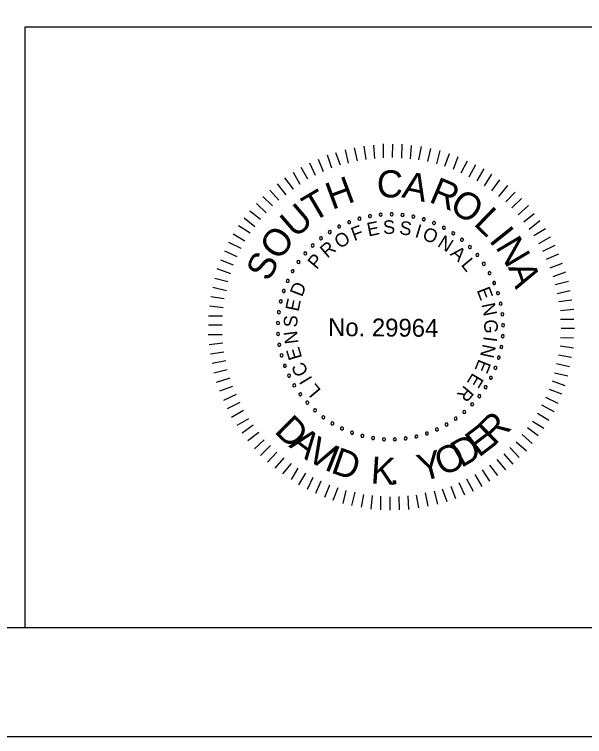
# Model space of a CAD drawing. Extents: x -133.1 to -97, y -110.1 to -88.1.
# Drawn here: x -110.556 to -107.945, y -110.103 to -106.796 of the extents above; entities that cross this region are included whole.
import ezdxf

# ---------------------------------------------------------------- set-up
doc = ezdxf.new("R2010")
doc.units = 0
for name, color, linetype in [('BR_BORDER LINES', 7, 'Continuous'), ('BR_TEXT', 7, 'Continuous'), ('Level 31', 7, 'Continuous')]:
    doc.layers.add(name, color=color, linetype=linetype)

msp = doc.modelspace()

# ---------------------------------------------------------------- linework, layer by layer
at = {"layer": 'BR_BORDER LINES'}
for p, q in [((-110.5071, -106.8526), (-105.1419, -106.8526)), ((-110.5071, -109.6027), (-110.5071, -106.8526)), ((-131.3076, -109.6027), (-97.6416, -109.6027))]:
    msp.add_line(p, q, dxfattribs=at)
at = {"layer": 'BR_TEXT'}
for p, q in [((-108.9059, -107.4556), (-108.9097, -107.3946)), ((-108.8664, -107.4533), (-108.8658, -107.389)), ((-108.8243, -107.4511), (-108.8238, -107.3893)), ((-108.7823, -107.454), (-108.78, -107.3897)), ((-108.742, -107.4569), (-108.7372, -107.396)), ((-109.0623, -107.4869), (-109.0842, -107.4292)), ((-109.0262, -107.4769), (-109.0394, -107.4159)), ((-108.9849, -107.467), (-108.999, -107.4076)), ((-108.9454, -107.4595), (-108.9543, -107.3986)), ((-108.7034, -107.4615), (-108.6926, -107.4007)), ((-108.6631, -107.4696), (-108.6489, -107.4105)), ((-108.622, -107.4802), (-108.606, -107.4195)), ((-109.1406, -107.5163), (-109.1642, -107.4603)), ((-109.1019, -107.4995), (-109.1229, -107.4409)), ((-108.5852, -107.4908), (-108.5633, -107.4335)), ((-108.5458, -107.504), (-108.5239, -107.4459)), ((-109.2122, -107.5509), (-109.2426, -107.4966)), ((-109.1777, -107.5332), (-109.2039, -107.4771)), ((-108.5099, -107.5215), (-108.482, -107.4659)), ((-108.474, -107.539), (-108.4427, -107.4834)), ((-109.2475, -107.5746), (-109.278, -107.5203)), ((-108.4364, -107.5573), (-108.4042, -107.5035)), ((-108.4031, -107.5816), (-108.3692, -107.5278)), ((-109.2786, -107.5958), (-109.3177, -107.5449)), ((-108.3699, -107.6033), (-108.3334, -107.553)), ((-109.3123, -107.6213), (-109.3522, -107.5712)), ((-108.3375, -107.6293), (-108.2968, -107.5799)), ((-109.3745, -107.6731), (-109.4188, -107.629)), ((-109.3451, -107.6459), (-109.3868, -107.6009)), ((-108.3059, -107.6545), (-108.2627, -107.6102)), ((-109.4039, -107.7038), (-109.4474, -107.6614)), ((-108.2779, -107.6822), (-108.2346, -107.6388)), ((-108.2498, -107.7133), (-108.2022, -107.6716)), ((-109.4551, -107.7686), (-109.5046, -107.7287)), ((-109.4291, -107.7353), (-109.4786, -107.6963)), ((-108.2226, -107.7453), (-108.1759, -107.707)), ((-108.1988, -107.779), (-108.1496, -107.7399)), ((-109.4768, -107.7976), (-109.5306, -107.7645)), ((-108.1768, -107.8083), (-108.1242, -107.7761)), ((-109.5012, -107.8343), (-109.5549, -107.8021)), ((-108.1548, -107.8454), (-108.1013, -107.8141)), ((-109.5186, -107.8685), (-109.575, -107.8405)), ((-108.137, -107.8799), (-108.0793, -107.8529)), ((-109.5361, -107.9052), (-109.5933, -107.8798)), ((-108.1193, -107.9169), (-108.0624, -107.8925)), ((-109.5536, -107.9437), (-109.6117, -107.9218)), ((-108.1025, -107.9557), (-108.0456, -107.9347)), ((-109.5659, -107.9839), (-109.6275, -107.9611)), ((-108.0891, -107.9961), (-108.0314, -107.9743)), ((-109.5782, -108.0199), (-109.639, -108.0048)), ((-108.079, -108.0322), (-108.0189, -108.0181)), ((-109.5854, -108.0619), (-109.6479, -108.0459)), ((-108.0708, -108.0744), (-108.0106, -108.0594)), ((-109.596, -108.0978), (-109.6569, -108.0896)), ((-108.0625, -108.1105), (-108.0033, -108.1032)), ((-109.6006, -108.139), (-109.6624, -108.1316)), ((-108.056, -108.1517), (-107.995, -108.1454)), ((-109.6035, -108.1784), (-109.6679, -108.1779)), ((-108.0546, -108.1912), (-107.9945, -108.1917)), ((-109.6056, -108.2196), (-109.6682, -108.219)), ((-108.0524, -108.2324), (-107.9915, -108.2329)), ((-109.6042, -108.2625), (-109.6686, -108.2637)), ((-108.0553, -108.2753), (-107.9952, -108.2775)), ((-109.602, -108.3012), (-109.6638, -108.3083)), ((-108.0574, -108.3139), (-107.9965, -108.3221)), ((-109.598, -108.3424), (-109.659, -108.3513)), ((-108.0645, -108.355), (-108.0054, -108.365)), ((-109.5881, -108.3819), (-109.6508, -108.3951)), ((-108.0735, -108.3944), (-108.0135, -108.4087)), ((-109.5815, -108.4241), (-109.6426, -108.4381)), ((-108.0824, -108.4364), (-108.0224, -108.4515)), ((-109.5698, -108.461), (-109.6318, -108.482)), ((-108.093, -108.4732), (-108.0357, -108.4951)), ((-109.5582, -108.4997), (-109.6167, -108.5207)), ((-108.107, -108.5117), (-108.0506, -108.5337)), ((-109.5413, -108.5368), (-109.599, -108.5638)), ((-108.1245, -108.5485), (-108.0681, -108.5764)), ((-109.5244, -108.573), (-109.5813, -108.6025)), ((-108.1428, -108.5844), (-108.0856, -108.6149)), ((-109.5076, -108.61), (-109.5619, -108.6413)), ((-108.1612, -108.6211), (-108.1082, -108.6533)), ((-109.4838, -108.6471), (-109.5382, -108.6784)), ((-109.4626, -108.6765), (-109.5127, -108.713)), ((-108.2063, -108.6868), (-108.1577, -108.7242)), ((-108.1838, -108.6579), (-108.1317, -108.69)), ((-109.4372, -108.7101), (-109.4873, -108.7492)), ((-108.2306, -108.7201), (-108.1846, -108.76)), ((-109.4125, -108.7438), (-109.4567, -108.7847)), ((-108.2583, -108.7533), (-108.2115, -108.7949)), ((-109.3836, -108.7698), (-109.4286, -108.8149)), ((-108.2869, -108.7789), (-108.2444, -108.8247)), ((-109.3547, -108.8001), (-109.3971, -108.8461)), ((-108.3155, -108.8087), (-108.273, -108.8553)), ((-109.3222, -108.8261), (-109.363, -108.873)), ((-109.289, -108.8521), (-109.3289, -108.8998)), ((-108.3474, -108.8341), (-108.3075, -108.8817)), ((-109.2583, -108.8738), (-109.2896, -108.9259)), ((-108.4139, -108.8808), (-108.3808, -108.9334)), ((-108.3802, -108.8596), (-108.3446, -108.908)), ((-109.2233, -108.8964), (-109.2546, -108.9502)), ((-109.1891, -108.9164), (-109.2162, -108.972)), ((-108.4475, -108.9028), (-108.4162, -108.9571)), ((-109.1523, -108.9339), (-109.1769, -108.9895)), ((-109.1139, -108.9514), (-109.1358, -109.0079)), ((-108.5216, -108.9391), (-108.4947, -108.9951)), ((-108.4855, -108.9222), (-108.455, -108.9783)), ((-109.0745, -108.9637), (-109.0973, -109.0219)), ((-109.0386, -108.9761), (-109.0528, -109.0351)), ((-108.9974, -108.9832), (-109.0126, -109.0449)), ((-108.6344, -108.9794), (-108.6194, -109.0387)), ((-108.5974, -108.9676), (-108.5764, -109.0262)), ((-108.5578, -108.956), (-108.5368, -109.0128)), ((-108.9581, -108.9947), (-108.968, -109.053)), ((-108.9186, -108.9993), (-108.9234, -109.0611)), ((-108.8792, -109.0022), (-108.8797, -109.064)), ((-108.8372, -109.0052), (-108.8377, -109.0661)), ((-108.7951, -109.0029), (-108.7939, -109.0648)), ((-108.7547, -109.0007), (-108.7509, -109.0625)), ((-108.7161, -108.9967), (-108.7062, -109.0552)), ((-108.6756, -108.9859), (-108.6624, -109.0478))]:
    msp.add_line(p, q, dxfattribs=at)
for centre, start, end in [((-108.9763, -107.7311), 16.1422, 196.1422), ((-108.9278, -107.7196), 10.6038, 190.6038), ((-108.9278, -107.7196), 190.6038, 10.6038), ((-108.8784, -107.7129), 5.0653, 185.0653), ((-108.8784, -107.7129), 185.0653, 5.0653), ((-108.8286, -107.711), 359.5268, 179.5268), ((-108.8286, -107.711), 179.5268, 359.5268), ((-108.7789, -107.714), 173.9884, 353.9884), ((-108.7789, -107.714), 353.9884, 173.9884), ((-108.7296, -107.7217), 168.4499, 348.4499), ((-108.7296, -107.7217), 348.4499, 168.4499), ((-108.6814, -107.7341), 342.9114, 162.9114), ((-109.0689, -107.7676), 27.2191, 207.2191), ((-109.0235, -107.7471), 21.6807, 201.6807), ((-109.0235, -107.7471), 201.6807, 21.6807), ((-108.9763, -107.7311), 196.1422, 16.1422), ((-108.6814, -107.7341), 162.9114, 342.9114), ((-108.6345, -107.7511), 157.373, 337.373), ((-108.6345, -107.7511), 337.373, 157.373), ((-109.1121, -107.7925), 32.7576, 212.7576), ((-109.1121, -107.7925), 212.7576, 32.7576), ((-109.0689, -107.7676), 207.2191, 27.2191), ((-108.5896, -107.7726), 151.8345, 331.8345), ((-108.5896, -107.7726), 331.8345, 151.8345), ((-108.5469, -107.7983), 146.2961, 326.2961), ((-108.5469, -107.7983), 326.2961, 146.2961), ((-109.1527, -107.8213), 38.2961, 218.2961), ((-109.1527, -107.8213), 218.2961, 38.2961), ((-108.5069, -107.828), 140.7576, 320.7576), ((-108.5069, -107.828), 320.7576, 140.7576), ((-109.1903, -107.854), 43.8345, 223.8345), ((-109.1903, -107.854), 223.8345, 43.8345), ((-108.4699, -107.8614), 135.2191, 315.2191), ((-108.4699, -107.8614), 315.2191, 135.2191), ((-109.2246, -107.8901), 49.373, 229.373), ((-109.2246, -107.8901), 229.373, 49.373), ((-108.4363, -107.8982), 129.6807, 309.6807), ((-108.4363, -107.8982), 309.6807, 129.6807), ((-109.2553, -107.9294), 54.9114, 234.9114), ((-109.2553, -107.9294), 234.9114, 54.9114), ((-108.4065, -107.9381), 124.1422, 304.1422), ((-108.4065, -107.9381), 304.1422, 124.1422), ((-109.282, -107.9715), 60.4499, 240.4499), ((-109.282, -107.9715), 240.4499, 60.4499), ((-108.3806, -107.9807), 118.6038, 298.6038), ((-108.3806, -107.9807), 298.6038, 118.6038), ((-109.3045, -108.0159), 65.9884, 245.9884), ((-109.3045, -108.0159), 245.9884, 65.9884), ((-108.359, -108.0256), 113.0653, 293.0653), ((-108.359, -108.0256), 293.0653, 113.0653), ((-109.3227, -108.0623), 71.5268, 251.5268), ((-109.3227, -108.0623), 251.5268, 71.5268), ((-108.3418, -108.0724), 107.5268, 287.5268), ((-108.3418, -108.0724), 287.5268, 107.5268), ((-109.3363, -108.1103), 77.0653, 257.0653), ((-109.3363, -108.1103), 257.0653, 77.0653), ((-108.3292, -108.1206), 101.9884, 281.9884), ((-108.3292, -108.1206), 281.9884, 101.9884), ((-109.3452, -108.1593), 82.6038, 262.6038), ((-109.3452, -108.1593), 262.6038, 82.6038), ((-108.3213, -108.1698), 96.4499, 276.4499), ((-108.3213, -108.1698), 276.4499, 96.4499), ((-109.3493, -108.209), 88.1422, 268.1422), ((-109.3493, -108.209), 268.1422, 88.1422), ((-108.3182, -108.2195), 90.9114, 270.9114), ((-108.3182, -108.2195), 270.9114, 90.9114), ((-109.3486, -108.2588), 93.6807, 273.6807), ((-109.3486, -108.2588), 273.6807, 93.6807), ((-108.3199, -108.2693), 85.373, 265.373), ((-108.3199, -108.2693), 265.373, 85.373), ((-109.3431, -108.3083), 99.2191, 279.2191), ((-109.3431, -108.3083), 279.2191, 99.2191), ((-108.3265, -108.3187), 79.8345, 259.8345), ((-108.3265, -108.3187), 259.8345, 79.8345), ((-109.3328, -108.3571), 104.7576, 284.7576), ((-109.3328, -108.3571), 284.7576, 104.7576), ((-108.3377, -108.3673), 74.2961, 254.2961), ((-108.3377, -108.3673), 254.2961, 74.2961), ((-109.3179, -108.4046), 110.2961, 290.2961), ((-109.3179, -108.4046), 290.2961, 110.2961), ((-108.3536, -108.4145), 68.7576, 248.7576), ((-108.3536, -108.4145), 248.7576, 68.7576), ((-109.2985, -108.4505), 115.8345, 295.8345), ((-109.2985, -108.4505), 295.8345, 115.8345), ((-108.374, -108.46), 63.2191, 243.2191), ((-108.374, -108.46), 243.2191, 63.2191), ((-109.2747, -108.4943), 121.373, 301.373), ((-109.2747, -108.4943), 301.373, 121.373), ((-108.3986, -108.5033), 57.6807, 237.6807), ((-108.3986, -108.5033), 237.6807, 57.6807), ((-109.2468, -108.5356), 126.9114, 306.9114), ((-109.2468, -108.5356), 306.9114, 126.9114), ((-108.4273, -108.544), 52.1422, 232.1422), ((-108.4273, -108.544), 232.1422, 52.1422), ((-109.2151, -108.574), 132.4499, 312.4499), ((-109.2151, -108.574), 312.4499, 132.4499), ((-108.4599, -108.5818), 46.6038, 226.6038), ((-108.4599, -108.5818), 226.6038, 46.6038), ((-109.1798, -108.6092), 137.9884, 317.9884), ((-109.1798, -108.6092), 317.9884, 137.9884), ((-108.4959, -108.6162), 41.0653, 221.0653), ((-108.4959, -108.6162), 221.0653, 41.0653), ((-109.1413, -108.6408), 143.5268, 323.5268), ((-109.1413, -108.6408), 323.5268, 143.5268), ((-108.5351, -108.647), 35.5268, 215.5268), ((-108.5351, -108.647), 215.5268, 35.5268), ((-109.0999, -108.6685), 149.0653, 329.0653), ((-109.0999, -108.6685), 329.0653, 149.0653), ((-109.056, -108.6921), 334.6038, 154.6038), ((-108.577, -108.6739), 29.9884, 209.9884), ((-108.577, -108.6739), 209.9884, 29.9884), ((-109.056, -108.6921), 154.6038, 334.6038), ((-109.01, -108.7114), 160.1422, 340.1422), ((-109.01, -108.7114), 340.1422, 160.1422), ((-108.9624, -108.7261), 345.6807, 165.6807), ((-108.6677, -108.7149), 18.9114, 198.9114), ((-108.6677, -108.7149), 198.9114, 18.9114), ((-108.6214, -108.6966), 24.4499, 204.4499), ((-108.6214, -108.6966), 204.4499, 24.4499), ((-108.9624, -108.7261), 165.6807, 345.6807), ((-108.9136, -108.7362), 171.2191, 351.2191), ((-108.9136, -108.7362), 351.2191, 171.2191), ((-108.8641, -108.7415), 356.7576, 176.7576), ((-108.8641, -108.7415), 176.7576, 356.7576), ((-108.8142, -108.742), 2.2961, 182.2961), ((-108.8142, -108.742), 182.2961, 2.2961), ((-108.7646, -108.7377), 7.8345, 187.8345), ((-108.7646, -108.7377), 187.8345, 7.8345), ((-108.7156, -108.7287), 13.373, 193.373), ((-108.7156, -108.7287), 193.373, 13.373)]:
    msp.add_arc(centre, 0.00701, start, end, dxfattribs=at)
at = {"layer": 'Level 31'}
msp.add_lwpolyline([(-133.1409, -110.1026), (-97.141, -110.1026), (-97.141, -88.1026), (-133.1409, -88.1026)], close=True, dxfattribs=at)

# ---------------------------------------------------------------- texts
at = {"layer": 'BR_TEXT'}
for s, height, rotation, p in [('C', 0.1241, 359.5482, (-108.8971, -107.6334)), ('A', 0.1241, 348.1981, (-108.7857, -107.6327)), ('H', 0.1241, 20.3637, (-109.1015, -107.6918)), ('R', 0.1241, 337.4344, (-108.6624, -107.6525)), ('T', 0.1241, 30.4992, (-109.1894, -107.7493)), ('O', 0.1239, 326.5869, (-108.5702, -107.6893)), ('U', 0.1241, 40.8022, (-109.2706, -107.824)), ('L', 0.1241, 315.9488, (-108.4576, -107.7571)), ('F', 0.0622, 20.6127, (-109.0002, -107.8346)), ('E', 0.0622, 11.4103, (-108.9351, -107.813)), ('S', 0.0622, 2.208, (-108.8672, -107.802)), ('S', 0.0622, 352.6608, (-108.796, -107.8022)), ('I', 0.0622, 343.1136, (-108.7257, -107.8142)), ('O', 0.1241, 52.0267, (-109.3451, -107.928)), ('O', 0.0622, 338.4392, (-108.6923, -107.8243)), ('I', 0.1241, 308.6613, (-108.3862, -107.8313)), ('O', 0.0622, 30.8477, (-109.0676, -107.8707)), ('N', 0.0622, 328.2042, (-108.6227, -107.8557)), ('N', 0.1241, 300.7037, (-108.3556, -107.8607)), ('R', 0.0622, 40.3949, (-109.1237, -107.9145)), ('S', 0.1239, 63.2511, (-109.3905, -108.0236)), ('P', 0.0622, 49.9421, (-109.1718, -107.9671)), ('A', 0.0622, 318.657, (-108.5637, -107.8958)), ('L', 0.0622, 309.4546, (-108.5139, -107.9431)), ('A', 0.1241, 289.4792, (-108.2964, -107.9538)), ('D', 0.0622, 69.0364, (-109.2388, -108.0924)), ('E', 0.0622, 291.049, (-108.44, -108.0584)), ('E', 0.0622, 78.2388, (-109.2553, -108.1591)), ('N', 0.0622, 281.8466, (-108.4179, -108.1234)), ('S', 0.0622, 87.786, (-109.2611, -108.2301)), ('No. 29964', 0.08175, 359.5268, (-109.1199, -108.2685)), ('G', 0.0622, 272.2995, (-108.4061, -108.1937)), ('N', 0.0622, 97.3332, (-109.2549, -108.3011)), ('I', 0.0622, 262.4084, (-108.4065, -108.2675)), ('E', 0.0622, 106.5355, (-109.2379, -108.3677)), ('N', 0.0622, 257.7339, (-108.411, -108.3022)), ('E', 0.0622, 248.1867, (-108.4291, -108.3711)), ('C', 0.0622, 116.4266, (-109.208, -108.4352)), ('I', 0.0622, 121.1011, (-109.1899, -108.4651)), ('E', 0.0622, 238.9844, (-108.457, -108.4339)), ('L', 0.0622, 129.9595, (-109.1493, -108.5172)), ('R', 0.0622, 229.782, (-108.4947, -108.4913)), ('D', 0.1236, 315.4053, (-109.3698, -108.7078)), ('R', 0.1236, 44.5947, (-108.3589, -108.7734)), ('E', 0.1236, 37.5339, (-108.4295, -108.8273)), ('A', 0.1236, 322.8377, (-109.3032, -108.7735)), ('V', 0.1236, 330.5179, (-109.226, -108.8317)), ('D', 0.1236, 30.1015, (-108.5104, -108.8742)), ('I', 0.1236, 338.1981, (-109.1418, -108.8791)), ('D', 0.1236, 340.7995, (-109.1119, -108.8925)), ('O', 0.1236, 22.4212, (-108.5997, -108.9113)), ('Y', 0.1236, 14.8649, (-108.6915, -108.9358)), ('K', 0.1236, 356.098, (-108.9267, -108.943)), ('.', 0.1236, 3.1588, (-108.838, -108.9494))]:
    msp.add_text(s, height=height, rotation=rotation, dxfattribs=at).set_placement(p)

doc.saveas('drawing.dxf')
